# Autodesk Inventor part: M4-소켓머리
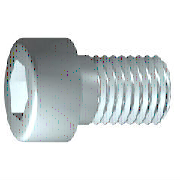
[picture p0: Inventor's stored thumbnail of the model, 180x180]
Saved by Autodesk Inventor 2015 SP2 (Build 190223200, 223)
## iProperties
IsCustomPart: 0
Created: 2009-02
Part Number: M4-소켓머리
Material: 강, 연강
Description: 6각머리 태핑 나사
Document SubType Name: Modeling
Standard: KS B 1003
Designer: 한국산업디자인학원 [http://gmhk.co.kr]
Standards Organization: KS
Language: ko-KR
Size Designation: M 4 x 12
Categories: <MemberInstance><Categories><Category DisplayName="조임쇠" InternalName="e4da775c-781d-43d5-af7c-5136215cf5a6" Mnemonic="FSTN"><Category DisplayName="볼트" InternalN
Density: 1 g/cm^3
Appearance: _시험-금속-강(연마)
Author: pww
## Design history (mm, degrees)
sketch "스케치1"
  geometry: L1 (-1, 0)-(12, 0); L2 (12, 0)-(12, 2); L3 (12, 2)-(1.75, 2); L4 (1.75, 2)-(1.32, 2); L5 (1.32, 2)-(0, 2); L6 (0, 2)-(0, 3.5); L7 (0, 3.5)-(-4, 3.5); L8 (-4, 3.5)-(-4, 1.732); L9 (-4, 1.732)-(-2, 1.732); L10 (-2, 1.732)-(-1, 0); L11 (-7.2, 0)-(15.2, 0) reference; L12 (0, -0.7)-(0, 4.2) reference; L13 (1.75, 2)-(0, 2)
  constraints: 22 end point, 6 parallel, 2 collinear, 2 perpendicular, 1 horizontal, 1 point on line
  dimensions: "d1" = 10.25 distance from line of L3.end L2 (= GEL); "d2" = 0.42952 distance of L4.end L3.end (computed from GAL); "d3" = 4 distance between parallel lines of L8 L6 (= KOH); "d4" = 2 distance of L8.end L9.end (= INTI); "d5" = 60 deg angle of L10 L1; "d6" = 4 diameter of L3 L1 (= GD); "d7" = 4 diameter of L5 L1 (= BDM); "d8" = 3.4641 diameter of L9 L1 (= 1.1547 x SW); "d9" = 7 diameter of L7 L1 (= KOD); "d26" = 12 distance between parallel lines of L12 L2 (= NLG)
revolve "본체" sketch "스케치1" stored, may be unused: angle "d10" = 90 deg
sketch "스케치2"
  geometry: L1 (0, -4.9)-(0, 4.9) reference; L2 (-4.9, 0)-(4.9, 0) reference; L3 (1.732, 0)-(0.866, -1.5); L4 (0.866, -1.5)-(-0.866, -1.5); L5 (-0.866, -1.5)-(-1.732, 0); L6 (-1.732, 0)-(-0.866, 1.5); L7 (-0.866, 1.5)-(0.866, 1.5); L8 (0.866, 1.5)-(1.732, 0); 2 further points
  constraints: 12 end point, 1 coincident, 1 horizontal alignment, 1 point on line, 12 other
extrude "슬롯" join sketch "스케치2" stored distance "d11" = 10; taper "d12" = 0 deg
workplane "Work Plane1"
fillet "Fillet2" dims "d30" = 0.1 (= R)
body "Solid1"
fillet "모깎기1" dims "d17" = 0.4 (= RR)
feature "스레드" dims "d13" = 10.25 (= GEL), "d14" = 0
chamfer "모따기1" distance "d15" = 0.42941 (= -0.5 x SPD + 0.5 x GD); stored, may be unused: second distance "d16" = 0.42941 (= GUL), angle "d27" = 45 deg
other parameters: "GD" = 4 (= NND) [user parameter; used in 2 equation terms], "NLG" = 12 [user parameter; used in 1 equation term], "GEL" = 10.25 [user parameter; used in 2 equation terms], "KOD" = 7 [user parameter; used in 1 equation term], "KOH" = 4 [user parameter; used in 1 equation term], "INTI" = 2 [user parameter; used in 1 equation term], "GAL" = 0.42941 (= 0.61345 x PTC) [user parameter; used in 1 equation term], "GUL" = 0.42941 (= 0.61345 x PTC) [user parameter; used in 1 equation term], "BDM" = 4 (= NND) [user parameter; used in 1 equation term], "SW" = 3 [user parameter; used in 2 equation terms], "RR" = 0.4 [user parameter; used in 1 equation term], "SPD" = 3.14117 (= NND - 1.2269 x PTC) [user parameter; used in 1 equation term], "d19" = 0, "d28" = 0, "d29" = 0, "R" = 0.1 [user parameter; used in 1 equation term], "PHH" = 0.2 [user parameter], "GD1" = 3.14117 (= THREADDIA - 1.2269 x PTC) [user parameter], "THREADDIA" = 4 [user parameter; used in 1 equation term], "FAWI" = 45 deg [user parameter], "TPU" = 14.28571 (computed from PTC) [user parameter], "PTC" = 0.7 [user parameter; used in 5 equation terms], "NND" = 4 [user parameter; used in 3 equation terms], "TOA" = 30 deg [user parameter], "E0" = 3.465 (= 1.155 x SW) [user parameter]
